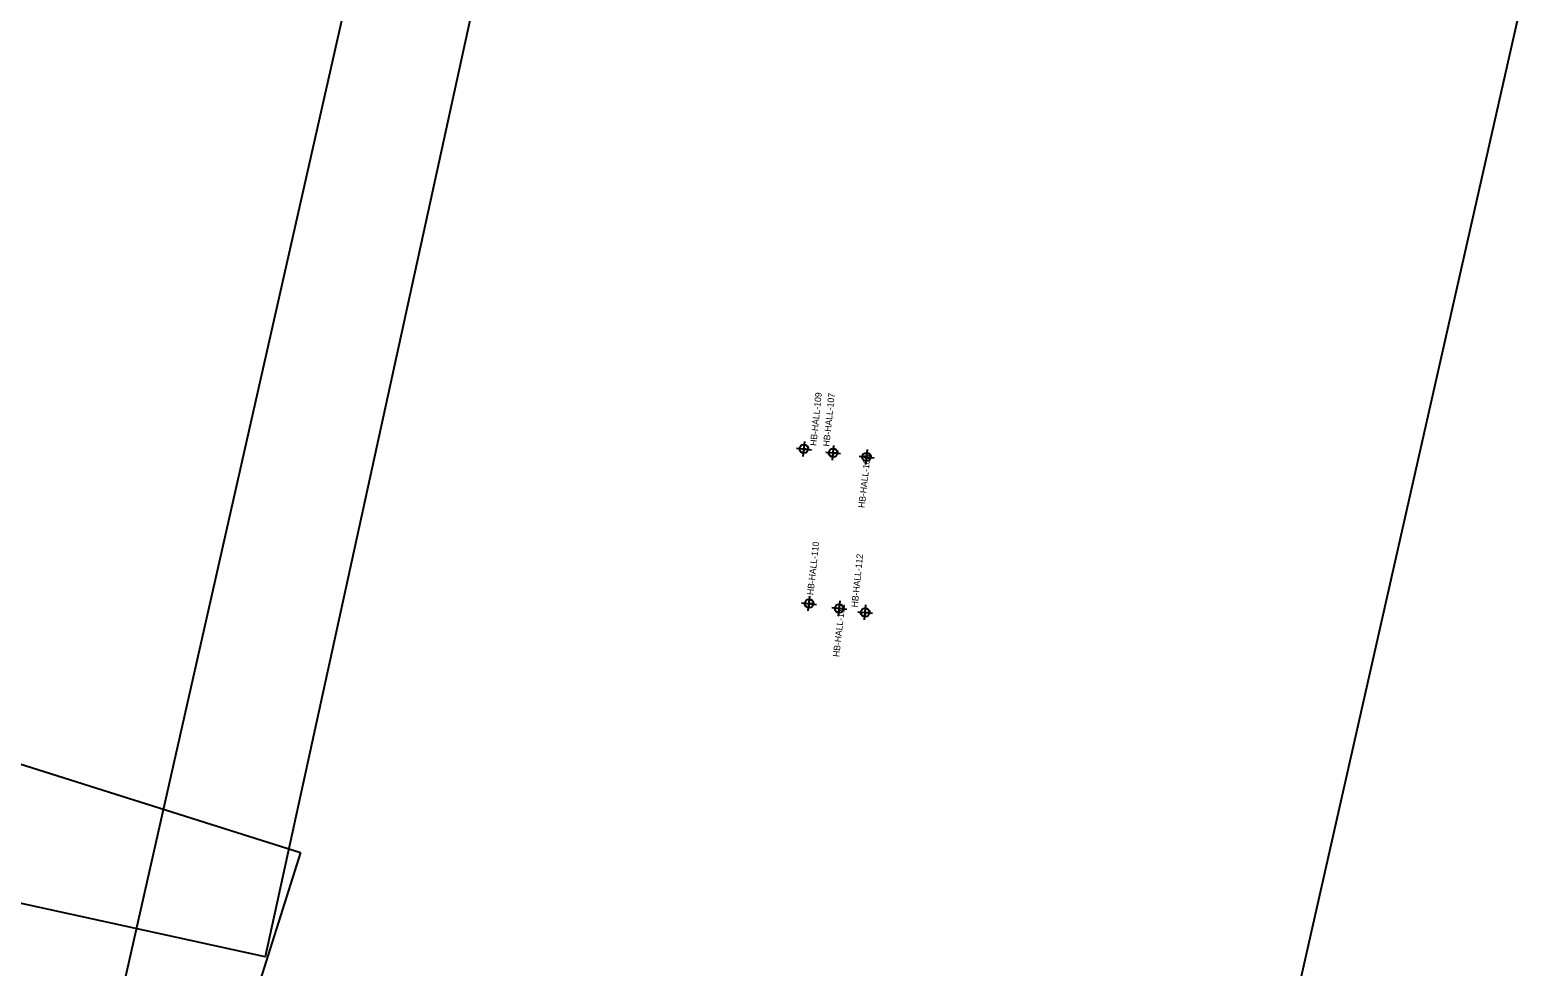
# Model space of a CAD drawing. Extents: x 1136334 to 1137758, y 528745 to 531454.
# Drawn here: x 1137018 to 1137709, y 529623 to 530052 of the extents above; entities that cross this region are included whole.
import ezdxf

# ---------------------------------------------------------------- set-up
doc = ezdxf.new("R2010")
doc.units = 0
doc.layers.add('PLOT BOUNDARY', color=7, linetype='Continuous')
doc.layers.add('ROCKS', color=7, linetype='Continuous')

msp = doc.modelspace()

# ---------------------------------------------------------------- linework, layer by layer
at = {"layer": 'PLOT BOUNDARY'}
for points in [[(1137285.97, 530360.56), (1137125.85, 529627.85), (1136612.96, 529739.94), (1136773.08, 530472.64)], [(1137708.64, 530098.42), (1137543.37, 529366.86), (1137031.27, 529482.55), (1137196.54, 530214.11)], [(1137142.07, 529675.56), (1136916.06, 528960.42), (1136415.46, 529118.63), (1136641.47, 529833.77)]]:
    msp.add_lwpolyline(points, close=True, dxfattribs=at)
at = {"layer": 'ROCKS'}
for p, q in [((1137369.15, 529860.74), (1137376, 529860.03)), ((1137372.22, 529856.96), (1137372.93, 529863.81)), ((1137382.54, 529858.96), (1137389.38, 529858.25)), ((1137385.61, 529855.18), (1137386.32, 529862.03)), ((1137400.87, 529853.26), (1137401.64, 529860.11)), ((1137397.84, 529857.07), (1137404.68, 529856.3)), ((1137371.53, 529789.98), (1137378.37, 529789.21)), ((1137374.57, 529786.18), (1137375.34, 529793.02)), ((1137388.39, 529783.92), (1137389.15, 529790.76)), ((1137385.35, 529787.73), (1137392.19, 529786.96)), ((1137397.2, 529785.85), (1137404.05, 529785.14)), ((1137400.27, 529782.07), (1137400.98, 529788.92))]:
    msp.add_line(p, q, dxfattribs=at)
for points in [[(1137372.58, 529860.38), (1137372.38, 529858.43), (1137372.1, 529858.48), (1137371.84, 529858.56), (1137371.6, 529858.68), (1137371.34, 529858.86), (1137371.15, 529859.03), (1137370.93, 529859.31), (1137370.81, 529859.51), (1137370.66, 529859.94), (1137370.61, 529860.29), (1137370.62, 529860.59)], [(1137372.58, 529860.38), (1137372.78, 529862.34), (1137373.05, 529862.29), (1137373.31, 529862.21), (1137373.56, 529862.09), (1137373.82, 529861.91), (1137374, 529861.74), (1137374.23, 529861.46), (1137374.35, 529861.25), (1137374.5, 529860.82), (1137374.54, 529860.47), (1137374.54, 529860.18)], [(1137385.96, 529858.61), (1137385.76, 529856.65), (1137385.49, 529856.7), (1137385.23, 529856.78), (1137384.98, 529856.9), (1137384.72, 529857.08), (1137384.53, 529857.25), (1137384.31, 529857.53), (1137384.19, 529857.74), (1137384.04, 529858.17), (1137384, 529858.51), (1137384, 529858.81)], [(1137385.96, 529858.61), (1137386.16, 529860.56), (1137386.43, 529860.51), (1137386.7, 529860.43), (1137386.94, 529860.31), (1137387.2, 529860.13), (1137387.39, 529859.96), (1137387.61, 529859.68), (1137387.73, 529859.48), (1137387.88, 529859.05), (1137387.93, 529858.7), (1137387.92, 529858.4)], [(1137401.26, 529856.68), (1137401.48, 529858.64), (1137401.75, 529858.59), (1137402.01, 529858.5), (1137402.25, 529858.38), (1137402.51, 529858.2), (1137402.69, 529858.03), (1137402.92, 529857.74), (1137403.03, 529857.54), (1137403.18, 529857.11), (1137403.22, 529856.76), (1137403.21, 529856.46)], [(1137401.26, 529856.68), (1137401.04, 529854.73), (1137400.77, 529854.78), (1137400.51, 529854.87), (1137400.26, 529854.99), (1137400, 529855.17), (1137399.82, 529855.34), (1137399.59, 529855.63), (1137399.48, 529855.83), (1137399.33, 529856.26), (1137399.29, 529856.61), (1137399.3, 529856.9)], [(1137374.95, 529789.6), (1137374.73, 529787.64), (1137374.46, 529787.69), (1137374.2, 529787.78), (1137373.96, 529787.9), (1137373.7, 529788.08), (1137373.51, 529788.25), (1137373.29, 529788.54), (1137373.18, 529788.74), (1137373.03, 529789.17), (1137372.99, 529789.52), (1137373, 529789.82)], [(1137374.95, 529789.6), (1137375.17, 529791.55), (1137375.44, 529791.5), (1137375.7, 529791.42), (1137375.95, 529791.29), (1137376.21, 529791.12), (1137376.39, 529790.94), (1137376.61, 529790.66), (1137376.73, 529790.45), (1137376.88, 529790.02), (1137376.92, 529789.67), (1137376.91, 529789.38)], [(1137388.77, 529787.34), (1137388.99, 529789.3), (1137389.26, 529789.25), (1137389.52, 529789.16), (1137389.77, 529789.04), (1137390.03, 529788.86), (1137390.21, 529788.69), (1137390.43, 529788.4), (1137390.54, 529788.2), (1137390.69, 529787.77), (1137390.74, 529787.42), (1137390.73, 529787.12)], [(1137388.77, 529787.34), (1137388.55, 529785.39), (1137388.28, 529785.44), (1137388.02, 529785.53), (1137387.77, 529785.65), (1137387.51, 529785.83), (1137387.33, 529786), (1137387.11, 529786.29), (1137387, 529786.49), (1137386.85, 529786.92), (1137386.8, 529787.27), (1137386.81, 529787.56)], [(1137400.63, 529785.5), (1137400.42, 529783.54), (1137400.15, 529783.59), (1137399.89, 529783.67), (1137399.64, 529783.79), (1137399.38, 529783.97), (1137399.2, 529784.14), (1137398.97, 529784.42), (1137398.86, 529784.62), (1137398.71, 529785.06), (1137398.66, 529785.4), (1137398.67, 529785.7)], [(1137400.63, 529785.5), (1137400.83, 529787.45), (1137401.1, 529787.4), (1137401.36, 529787.32), (1137401.61, 529787.2), (1137401.87, 529787.02), (1137402.05, 529786.85), (1137402.28, 529786.57), (1137402.39, 529786.37), (1137402.55, 529785.94), (1137402.59, 529785.59), (1137402.59, 529785.29)]]:
    msp.add_lwpolyline(points, close=True, dxfattribs=at)
for centre in [(1137372.58, 529860.38), (1137385.96, 529858.61), (1137401.26, 529856.68), (1137374.95, 529789.6), (1137388.77, 529787.34), (1137400.63, 529785.5)]:
    msp.add_circle(centre, 1.97, dxfattribs=at)

# ---------------------------------------------------------------- texts
for s, rotation, p in [('HB-HALL-109', 84.0839, (1137378.25, 529861.68)), ('HB-HALL-107', 84.0839, (1137384.2, 529861.39)), ('HB-HALL-108', 83.58699, (1137400.36, 529833.24)), ('HB-HALL-110', 83.58699, (1137376.85, 529793.33)), ('HB-HALL-112', 84.0839, (1137397.16, 529787.71)), ('HB-HALL-111', 83.58699, (1137388.74, 529764.99))]:
    msp.add_text(s, height=2.9528, rotation=rotation, dxfattribs=at).set_placement(p)

doc.saveas('drawing.dxf')
